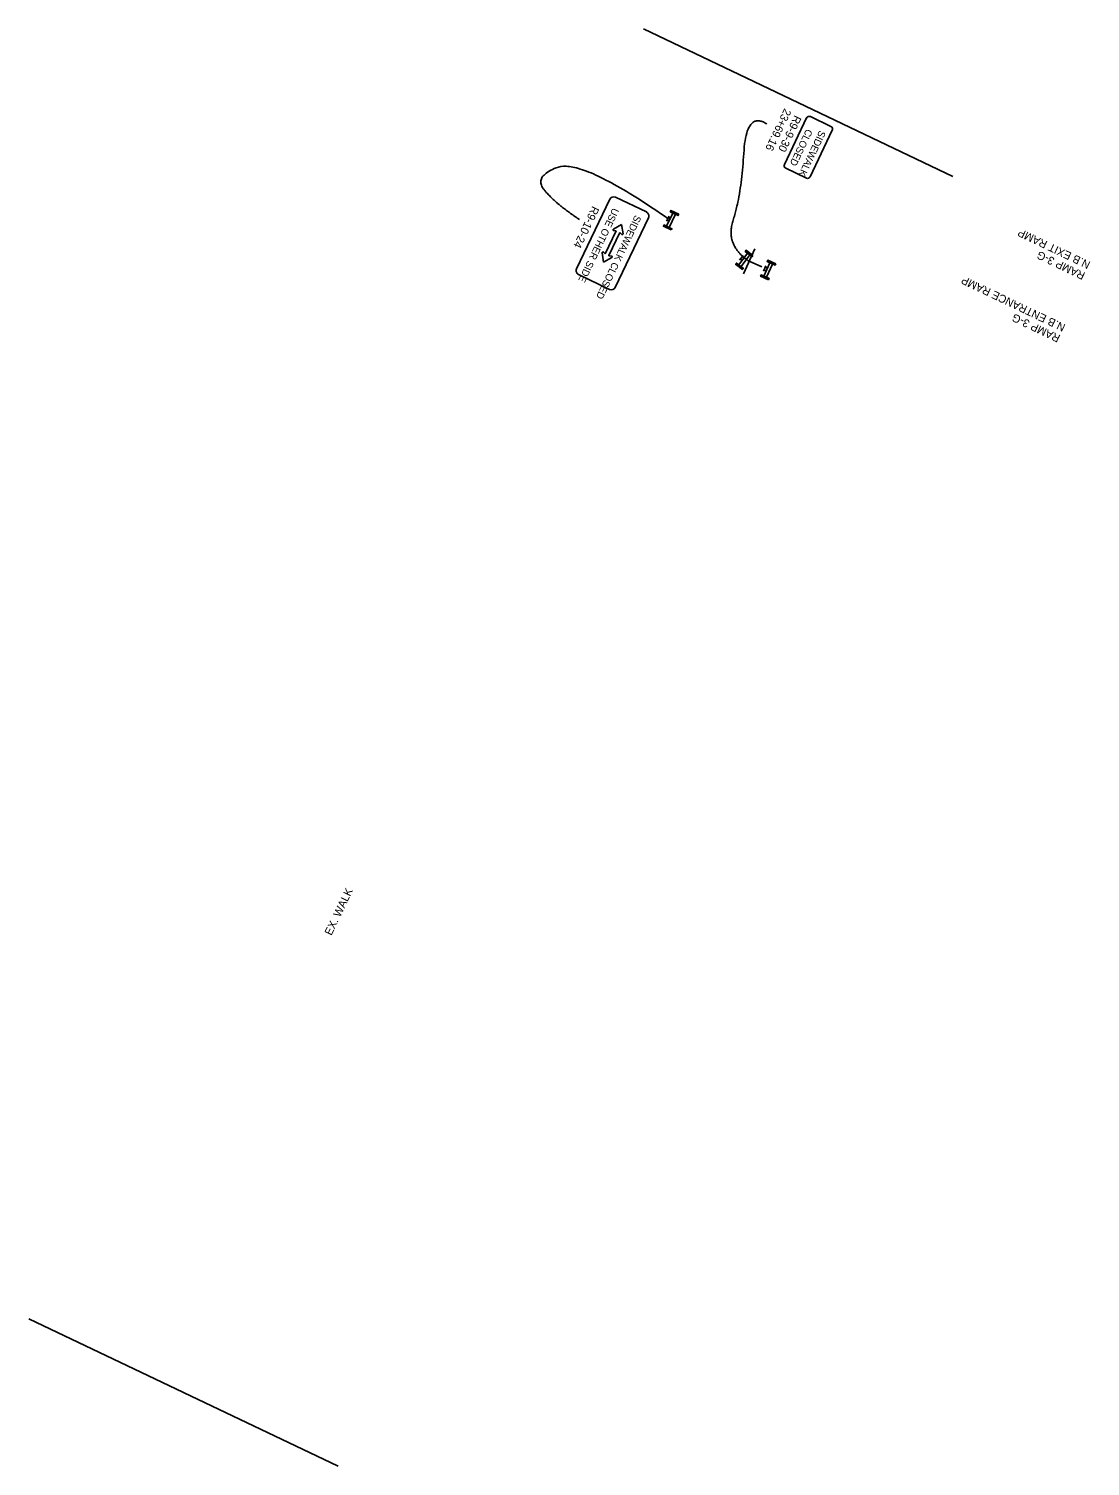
# Model space of a CAD drawing. Extents: x 186187 to 186558, y 352513 to 353016.
import ezdxf

# ---------------------------------------------------------------- set-up
doc = ezdxf.new("R2010")
doc.units = 0
for name, color, linetype in [('SH_Data', 7, 'Continuous'), ('SH_Masking', 7, 'Continuous'), ('SH_Text', 7, 'Continuous')]:
    doc.layers.add(name, color=color, linetype=linetype)

msp = doc.modelspace()

# ---------------------------------------------------------------- linework, layer by layer
at = {"layer": 'SH_Data'}
for p, q in [((186510.16, 352964.46), (186401.84, 353016.1)), ((186294.98, 352513.13), (186186.66, 352564.77))]:
    msp.add_line(p, q, dxfattribs=at)
at = {"layer": 'SH_Masking'}
for p, q in [((186412.13, 352951.62), (186409.94, 352947.02)), ((186413.05, 352951.18), (186410.86, 352946.58)), ((186394.14, 352947.59), (186391.31, 352945.99)), ((186394.68, 352944.39), (186394.14, 352947.59)), ((186409.91, 352948.73), (186410.78, 352950.57)), ((186410.82, 352948.86), (186410.13, 352949.19)), ((186411.25, 352949.78), (186410.56, 352950.11)), ((186411.5, 352949.1), (186411.5, 352949.1)), ((186389.73, 352936.71), (186393.57, 352944.76)), ((186391.01, 352941.03), (186391.01, 352941.03)), ((186391.41, 352945.48), (186392.3, 352945.36)), ((186393.57, 352944.76), (186393.56, 352944.75)), ((186393.57, 352944.76), (186394.22, 352944.14)), ((186387.34, 352937.67), (186387.89, 352934.47)), ((186388.46, 352937.3), (186387.8, 352937.92)), ((186387.89, 352934.47), (186390.71, 352936.07)), ((186389.73, 352936.7), (186389.73, 352936.71)), ((186390.61, 352936.57), (186389.73, 352936.7)), ((186438.25, 352937.56), (186435.19, 352933.49)), ((186435.5, 352935.17), (186436.72, 352936.8)), ((186436.42, 352935.12), (186435.8, 352935.58)), ((186439.07, 352936.95), (186436, 352932.88)), ((186437.03, 352935.93), (186436.42, 352936.39)), ((186436.9, 352930.34), (186440.78, 352939.12)), ((186437.13, 352935.22), (186437.13, 352935.22)), ((186438.84, 352934.73), (186443.23, 352932.79)), ((186443.88, 352931.28), (186444.73, 352933.13)), ((186446.06, 352934.2), (186443.95, 352929.57)), ((186444.79, 352931.42), (186444.1, 352931.74)), ((186445.21, 352932.35), (186444.52, 352932.67)), ((186446.98, 352933.78), (186444.87, 352929.15)), ((186445.47, 352931.67), (186445.47, 352931.67))]:
    msp.add_line(p, q, dxfattribs=at)
for points in [[(186458.93, 352984.88), (186451.18, 352968.63)], [(186467.48, 352981.9), (186460.26, 352985.35)], [(186460.21, 352964.32), (186467.95, 352980.57)], [(186451.65, 352967.29), (186458.87, 352963.85)], [(186378.43, 352932.07), (186390.05, 352956.44)], [(186392.05, 352957.15), (186402.88, 352951.99)], [(186403.59, 352949.99), (186391.97, 352925.62)], [(186392.3, 352945.36), (186388.46, 352937.31)], [(186389.97, 352924.91), (186379.14, 352930.07)]]:
    msp.add_lwpolyline(points, dxfattribs=at)
for points in [[(186414.19, 352951.21), (186411.43, 352952.52), (186411.21, 352952.06), (186413.97, 352950.75)], [(186411.56, 352945.69), (186408.81, 352947), (186409.02, 352947.46), (186411.78, 352946.15)], [(186440.18, 352936.75), (186437.74, 352938.58), (186437.44, 352938.17), (186439.88, 352936.34)], [(186436.51, 352931.86), (186434.07, 352933.7), (186434.38, 352934.11), (186436.82, 352932.27)], [(186448.12, 352933.82), (186445.34, 352935.09), (186445.13, 352934.62), (186447.91, 352933.36)], [(186445.59, 352928.26), (186442.81, 352929.53), (186443.02, 352929.99), (186445.8, 352928.72)]]:
    msp.add_lwpolyline(points, close=True, dxfattribs=at)
for centre, radius, start, end in [((186459.83, 352984.44), 1, 64.5098, 154.5098), ((186467.05, 352981), 1, 334.5098, 64.5098), ((186452.08, 352968.2), 1, 154.5098, 244.5098), ((186459.3, 352964.75), 1, 244.5098, 334.5098), ((186391.4, 352955.8), 1.5, 64.5098, 154.5098), ((186402.24, 352950.63), 1.5, 334.5098, 64.5098), ((186391.45, 352945.76), 0.274, 119.4305, 262.1476), ((186394.41, 352944.34), 0.274, 226.872, 9.589), ((186387.61, 352937.72), 0.274, 46.872, 189.589), ((186390.58, 352936.3), 0.274, 299.4305, 82.1476), ((186379.79, 352931.43), 1.5, 154.5098, 244.5098), ((186390.62, 352926.26), 1.5, 244.5098, 334.5098)]:
    msp.add_arc(centre, radius, start, end, dxfattribs=at)
at = {"layer": 'SH_Text'}
for points in [[(186438.84, 352934.73), (186430.37, 352940.34), (186436.09, 352957.95), (186437.85, 352987.5), (186445, 352982.78)], [(186379.47, 352949.32), (186370.99, 352954.93), (186363.26, 352964.47), (186380.22, 352970.72), (186410.38, 352949.73)]]:
    msp.add_open_spline(points, degree=2, dxfattribs=at)

# ---------------------------------------------------------------- texts
at = {"layer": 'SH_Masking'}
for s, height, rotation, p in [('23+69.16', 2.8, 244.5098, (186451.19, 352988.41)), ('R9-9-30', 2.8, 244.5098, (186454.73, 352986.07)), ('CLOSED', 2.5, 244.5098, (186458.89, 352981.25)), ('SIDEWALK', 2.5, 244.5098, (186463.5, 352980.74)), ('R9-10-24', 2.8, 244.5098, (186383.95, 352954.29)), ('USE OTHER SIDE', 2.5, 244.5098, (186391.12, 352953.61)), ('SIDEWALK CLOSED', 2.5, 244.5098, (186398.92, 352951.09)), ('N.B EXIT RAMP', 2.8, 154.5098, (186558.51, 352934.46)), ('RAMP 3-G', 2.8, 154.5098, (186556.71, 352930.67)), ('N.B ENTRANCE RAMP', 2.8, 154.5098, (186549.8, 352912.55)), ('RAMP 3-G', 2.8, 154.5098, (186547.99, 352908.76)), ('EX. WALK', 2.8, 64.5098, (186292.59, 352698.63))]:
    msp.add_text(s, height=height, rotation=rotation, dxfattribs=at).set_placement(p)

doc.saveas('drawing.dxf')
